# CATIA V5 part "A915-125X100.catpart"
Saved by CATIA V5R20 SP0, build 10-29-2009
Part number: A915-125X100
Source: Unknown
Property "A": "75.000"
Property "ARTICLENO": "A915-125X100"
Property "BOMINFO": "A915-125X100"
Property "CODE": "A915-125X100"
Property "CREATOR": "CADENAS GmbH"
Property "D": "13.500"
Property "D1": "20.000"
Property "FORM": "C"
Property "L": "100.000"
Property "L1": "25.000"
Property "L2": "50.000"
Property "LINA": "A915-125X100"
Property "NB": "A915-125X100"
Property "NBSYN": "$CODE."
Property "NN": "A915"
Property "NT": "VDI 3357 Wear Plates, steel"
Property "SCREW": "M12x25"
Property "SUPPLIER": "CF"
Property "T": "13.000"
Property "W": "125.000"
Bounding box of the stored display mesh (mm): x 0 to 20, y 0 to 100, z -62.5 to 62.5
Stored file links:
  C:\Users\borellobunino\Desktop\3D X SITO CF\A915\GSB_OILLESS_G22501125100\CATIAV5\A915-125X100.catpart
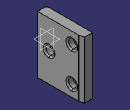
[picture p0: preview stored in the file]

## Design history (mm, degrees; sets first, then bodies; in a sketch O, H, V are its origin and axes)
Body1 "Geometry.1" (main body)
  Solid1 "A915-125X100.catpart": solid without history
